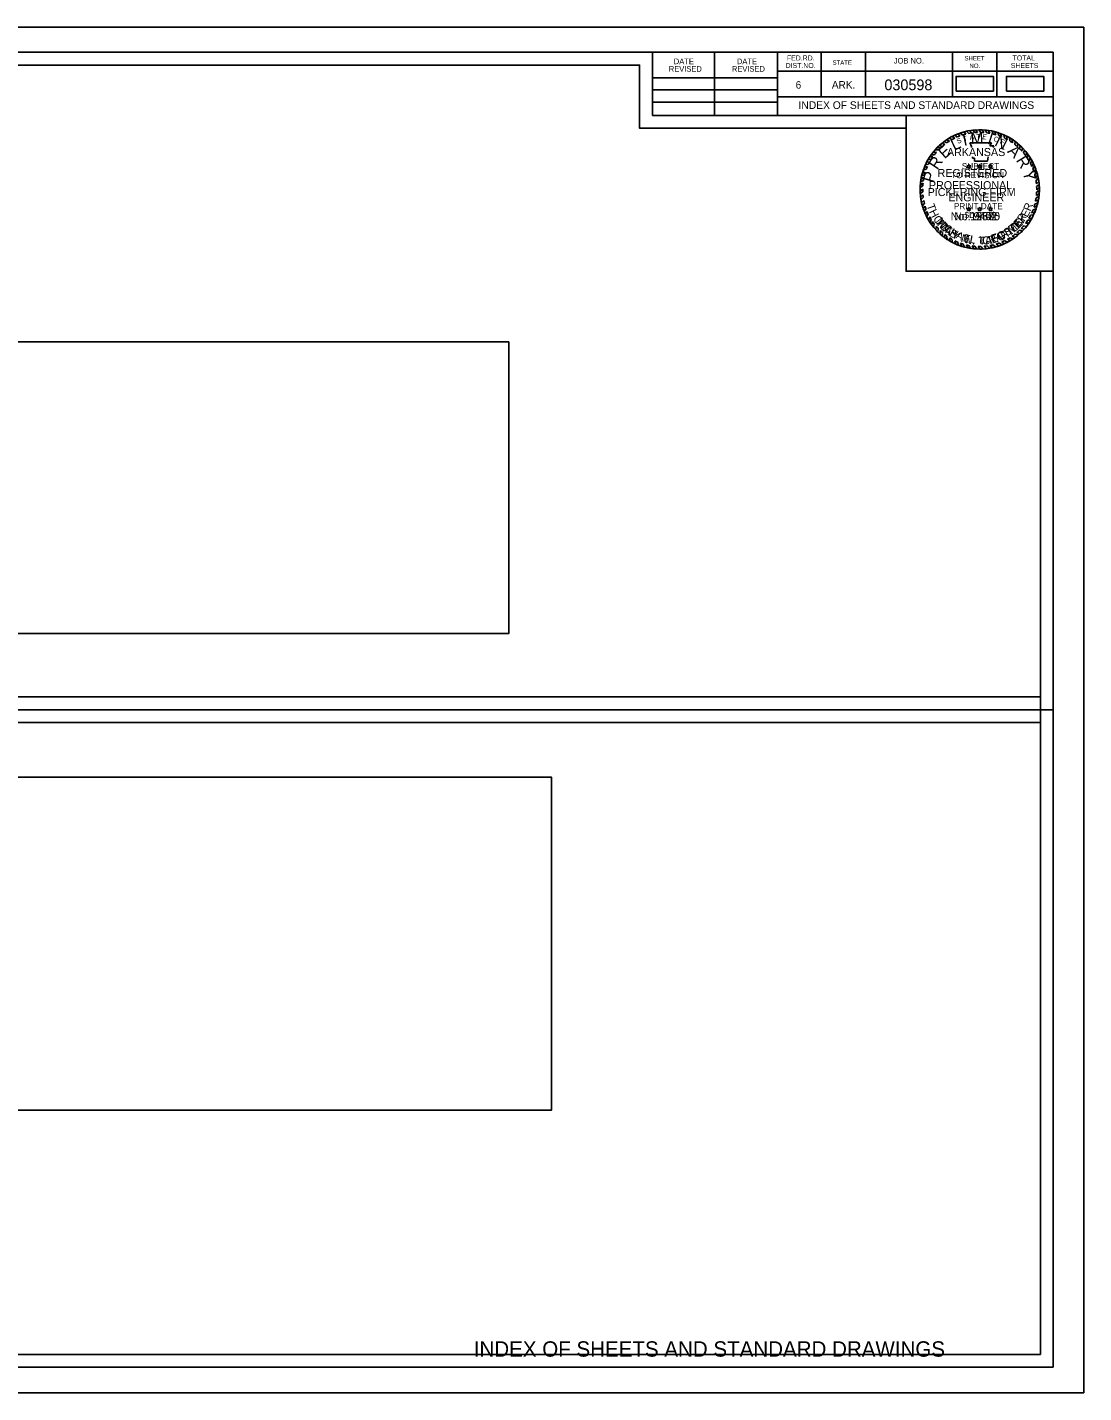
# Model space of a CAD drawing. Extents: x 1369905 to 1370238, y 380119 to 380332.
# Drawn here: x 1370072.9 to 1370238, y 380119.1 to 380332.4 of the extents above; entities that cross this region are included whole.
import ezdxf

# ---------------------------------------------------------------- set-up
doc = ezdxf.new("R2010")
doc.units = 0
for name, color, linetype in [('Default', 7, 'Continuous'), ('R_Border', 7, 'Continuous'), ('R_Border Notes', 7, 'Continuous'), ('R_Border Plan-Plan', 7, 'Continuous'), ('R_Border Title', 7, 'Continuous'), ('R_No Plot', 7, 'Continuous'), ('STAMP_PE_CRAFTON', 7, 'Continuous'), ('STAMP_PE_FOSTER', 7, 'Continuous'), ('STAMP_PE_SEAL-INFO', 7, 'Continuous'), ('STAMP_PE_TAEGTMEYER', 7, 'Continuous'), ('STAMP_PE_TXT', 7, 'Continuous'), ('STAMP_PRELIMINARY', 7, 'Continuous')]:
    doc.layers.add(name, color=color, linetype=linetype)

msp = doc.modelspace()

# ---------------------------------------------------------------- linework, layer by layer
at = {"layer": 'Default'}
for points in [[(1370218.03, 380322.43), (1370223.87, 380322.43), (1370223.87, 380324.74), (1370218.03, 380324.74)], [(1370225.9, 380322.43), (1370231.74, 380322.43), (1370231.74, 380324.74), (1370225.9, 380324.74)], [(1370003.51, 380237.69), (1370148.12, 380237.69), (1370148.12, 380283.26), (1370003.51, 380283.26)], [(1369996.82, 380163.24), (1370154.81, 380163.24), (1370154.81, 380215.25), (1369996.82, 380215.25)]]:
    msp.add_lwpolyline(points, close=True, dxfattribs=at)
at = {"layer": 'R_Border'}
for p, q in [((1369917.04, 380328.52), (1370233.22, 380328.52)), ((1370170.58, 380318.64), (1370170.58, 380328.52)), ((1370180.26, 380318.64), (1370180.26, 380328.52)), ((1370190.12, 380328.52), (1370190.12, 380318.64)), ((1370196.96, 380328.52), (1370196.96, 380321.58)), ((1370203.9, 380328.52), (1370203.9, 380321.58)), ((1370217.48, 380328.52), (1370217.48, 380321.58)), ((1370224.42, 380328.52), (1370224.42, 380321.58)), ((1370233.22, 380123.06), (1370233.22, 380328.52)), ((1370233.22, 380325.58), (1370190.12, 380325.58)), ((1370233.22, 380325.6), (1370233.22, 380325.6)), ((1370170.58, 380324.5), (1370190.12, 380324.5)), ((1370170.58, 380322.64), (1370190.12, 380322.64)), ((1370233.22, 380321.58), (1370190.12, 380321.58)), ((1370193.08, 380321.58), (1370233.22, 380321.58)), ((1370170.58, 380320.7), (1370190.12, 380320.7)), ((1370233.22, 380318.64), (1370170.58, 380318.64)), ((1370233.22, 380123.06), (1369917.04, 380123.06))]:
    msp.add_line(p, q, dxfattribs=at)
at = {"layer": 'R_Border Plan-Plan'}
msp.add_line((1369917.04, 380225.79), (1370233.22, 380225.79), dxfattribs=at)
at = {"layer": 'R_No Plot'}
for points in [[(1369904.63, 380332.42), (1370237.97, 380332.42), (1370237.97, 380119.08), (1369904.63, 380119.08)], [(1370231.22, 380227.79), (1369919.04, 380227.79), (1369919.04, 380326.52), (1370168.58, 380326.52), (1370168.58, 380316.64), (1370186.12, 380316.64), (1370210.22, 380316.64), (1370210.22, 380294.31), (1370231.22, 380294.31)], [(1369919.04, 380326.52), (1370168.58, 380326.52), (1370168.58, 380316.64), (1370186.12, 380316.64), (1370210.22, 380316.64), (1370210.22, 380294.31), (1370231.22, 380294.31), (1370231.22, 380125.06), (1369919.04, 380125.06)], [(1370210.22, 380318.64), (1370233.22, 380318.64), (1370233.22, 380294.31), (1370210.22, 380294.31)], [(1369919.04, 380223.79), (1370231.22, 380223.79), (1370231.22, 380125.06), (1369919.04, 380125.06)]]:
    msp.add_lwpolyline(points, close=True, dxfattribs=at)
at = {"layer": 'STAMP_PE_SEAL-INFO'}
for p, q in [((1370216.56, 380314.85), (1370217, 380314.65)), ((1370216.94, 380315.09), (1370217.38, 380314.87)), ((1370217.39, 380315.34), (1370217.86, 380315.12)), ((1370217.82, 380315.56), (1370218.21, 380315.28)), ((1370218.33, 380315.77), (1370218.63, 380315.45)), ((1370218.68, 380315.9), (1370219.06, 380315.59)), ((1370219.27, 380316.08), (1370219.56, 380315.73)), ((1370219.66, 380316.18), (1370220.01, 380315.84)), ((1370220.14, 380316.28), (1370220.44, 380315.91)), ((1370220.66, 380316.35), (1370220.94, 380315.97)), ((1370221.39, 380315.99), (1370221.08, 380316.39)), ((1370221.89, 380316), (1370221.61, 380316.41)), ((1370222.35, 380315.98), (1370222.09, 380316.4)), ((1370222.85, 380315.93), (1370222.56, 380316.37)), ((1370223.28, 380315.86), (1370223.02, 380316.32)), ((1370223.84, 380315.74), (1370223.67, 380316.2)), ((1370224.24, 380315.64), (1370224.08, 380316.11)), ((1370224.69, 380315.49), (1370224.55, 380315.97)), ((1370225.11, 380315.33), (1370224.97, 380315.83)), ((1370225.57, 380315.12), (1370225.47, 380315.62)), ((1370226.02, 380314.89), (1370225.93, 380315.4)), ((1370226.41, 380314.67), (1370226.37, 380315.17)), ((1370226.84, 380314.38), (1370226.81, 380314.9)), ((1370214.41, 380312.88), (1370214.96, 380312.9)), ((1370214.76, 380313.29), (1370215.28, 380313.25)), ((1370215.08, 380313.63), (1370215.62, 380313.59)), ((1370215.42, 380313.96), (1370215.88, 380313.82)), ((1370215.76, 380314.26), (1370216.29, 380314.16)), ((1370216.14, 380314.58), (1370216.59, 380314.38)), ((1370220.19, 380314.38), (1370223.54, 380314.38)), ((1370220.31, 380314.07), (1370220.19, 380314.38)), ((1370220.42, 380313.77), (1370220.31, 380314.07)), ((1370220.42, 380313.66), (1370220.42, 380313.77)), ((1370223.54, 380314.38), (1370223.31, 380313.89)), ((1370223.31, 380313.89), (1370223.94, 380313.89)), ((1370223.94, 380313.89), (1370223.8, 380313.66)), ((1370227.2, 380314.11), (1370227.24, 380314.6)), ((1370227.65, 380313.74), (1370227.67, 380314.27)), ((1370227.96, 380313.45), (1370228.03, 380313.95)), ((1370228.32, 380313.08), (1370228.39, 380313.6)), ((1370228.59, 380312.76), (1370228.73, 380313.23)), ((1370228.92, 380312.34), (1370229.05, 380312.84)), ((1370213.05, 380310.52), (1370213.55, 380310.66)), ((1370213.23, 380310.95), (1370213.74, 380311.05)), ((1370213.42, 380311.34), (1370213.92, 380311.4)), ((1370213.65, 380311.76), (1370214.14, 380311.78)), ((1370213.9, 380312.16), (1370214.42, 380312.2)), ((1370214.13, 380312.51), (1370214.64, 380312.5)), ((1370220.62, 380311.95), (1370220.59, 380312.17)), ((1370220.93, 380311.95), (1370220.62, 380311.95)), ((1370220.93, 380311.52), (1370220.93, 380311.95)), ((1370222.96, 380311.52), (1370220.93, 380311.52)), ((1370222.98, 380311.86), (1370222.96, 380311.52)), ((1370223.05, 380312.17), (1370222.98, 380311.86)), ((1370229.14, 380312.03), (1370229.32, 380312.49)), ((1370229.45, 380311.53), (1370229.63, 380312.02)), ((1370229.65, 380311.16), (1370229.87, 380311.61)), ((1370229.88, 380310.68), (1370230.1, 380311.16)), ((1370230.02, 380310.34), (1370230.28, 380310.78)), ((1370212.92, 380308.5), (1370212.47, 380308.27)), ((1370213, 380308.95), (1370212.54, 380308.71)), ((1370212.64, 380309.2), (1370213.11, 380309.39)), ((1370212.74, 380309.61), (1370213.22, 380309.78)), ((1370212.9, 380310.11), (1370213.38, 380310.25)), ((1370230.21, 380309.79), (1370230.48, 380310.27)), ((1370230.32, 380309.43), (1370230.61, 380309.88)), ((1370230.45, 380308.87), (1370230.77, 380309.32)), ((1370230.52, 380308.49), (1370230.87, 380308.84)), ((1370212.82, 380307.64), (1370212.4, 380307.38)), ((1370212.81, 380307.14), (1370212.4, 380306.81)), ((1370212.86, 380308.06), (1370212.42, 380307.78)), ((1370212.81, 380306.74), (1370212.42, 380306.41)), ((1370230.58, 380306.13), (1370231.02, 380306.39)), ((1370230.59, 380307.98), (1370230.96, 380308.32)), ((1370230.62, 380307.56), (1370231.01, 380307.86)), ((1370230.62, 380306.64), (1370231.04, 380306.92)), ((1370230.63, 380307.05), (1370231.04, 380307.37)), ((1370212.85, 380306.24), (1370212.47, 380305.88)), ((1370212.9, 380305.81), (1370212.54, 380305.44)), ((1370212.98, 380305.35), (1370212.64, 380304.98)), ((1370213.07, 380304.93), (1370212.76, 380304.52)), ((1370213.19, 380304.49), (1370212.9, 380304.07)), ((1370230.19, 380304.3), (1370230.68, 380304.5)), ((1370230.33, 380304.79), (1370230.8, 380305)), ((1370230.44, 380305.25), (1370230.9, 380305.44)), ((1370230.53, 380305.75), (1370230.97, 380305.97)), ((1370213.33, 380304.06), (1370213.05, 380303.65)), ((1370213.5, 380303.64), (1370213.24, 380303.21)), ((1370213.67, 380303.25), (1370213.44, 380302.79)), ((1370213.91, 380302.79), (1370213.72, 380302.3)), ((1370214.14, 380302.39), (1370213.96, 380301.92)), ((1370214.35, 380302.08), (1370214.24, 380301.53)), ((1370229.23, 380302.29), (1370229.71, 380302.28)), ((1370229.4, 380302.57), (1370229.9, 380302.62)), ((1370229.68, 380303.07), (1370230.16, 380303.14)), ((1370229.84, 380303.41), (1370230.32, 380303.5)), ((1370230.05, 380303.92), (1370230.53, 380304.05)), ((1370214.63, 380301.69), (1370214.52, 380301.16)), ((1370214.93, 380301.31), (1370214.84, 380300.79)), ((1370215.23, 380300.97), (1370215.17, 380300.45)), ((1370215.56, 380300.65), (1370215.53, 380300.12)), ((1370215.9, 380300.34), (1370215.9, 380299.81)), ((1370216.26, 380300.04), (1370216.28, 380299.52)), ((1370227.27, 380300.11), (1370227.74, 380299.97)), ((1370227.54, 380300.34), (1370228.01, 380300.21)), ((1370227.95, 380300.71), (1370228.39, 380300.57)), ((1370228.2, 380300.97), (1370228.68, 380300.88)), ((1370228.58, 380301.4), (1370229.05, 380301.32)), ((1370228.89, 380301.8), (1370229.4, 380301.8)), ((1370216.6, 380299.79), (1370216.63, 380299.27)), ((1370217.02, 380299.51), (1370217.09, 380299)), ((1370217.38, 380299.3), (1370217.47, 380298.79)), ((1370217.86, 380299.05), (1370218.01, 380298.53)), ((1370218.23, 380298.89), (1370218.4, 380298.37)), ((1370218.72, 380298.69), (1370218.93, 380298.19)), ((1370219.13, 380298.56), (1370219.36, 380298.07)), ((1370219.64, 380298.42), (1370219.85, 380297.95)), ((1370220.04, 380298.33), (1370220.28, 380297.88)), ((1370220.54, 380298.25), (1370220.78, 380297.81)), ((1370220.97, 380298.2), (1370221.25, 380297.78)), ((1370221.46, 380298.18), (1370221.76, 380297.76)), ((1370221.92, 380298.18), (1370222.26, 380297.78)), ((1370222.44, 380298.2), (1370222.76, 380297.82)), ((1370222.87, 380298.25), (1370223.25, 380297.89)), ((1370223.32, 380298.32), (1370223.71, 380297.98)), ((1370223.81, 380298.42), (1370224.19, 380298.1)), ((1370224.27, 380298.55), (1370224.69, 380298.25)), ((1370224.76, 380298.71), (1370225.21, 380298.44)), ((1370225.18, 380298.87), (1370225.61, 380298.61)), ((1370225.64, 380299.08), (1370226.13, 380298.87)), ((1370226.05, 380299.3), (1370226.47, 380299.06)), ((1370226.47, 380299.54), (1370226.91, 380299.35)), ((1370226.81, 380299.77), (1370227.25, 380299.58))]:
    msp.add_line(p, q, dxfattribs=at)
for radius, start, end in [(9.32, 123.6199, 126.5906), (9.32, 117.6544, 120.8099), (8.91, 115.6869, 119.1583), (9.32, 111.3124, 114.7026), (8.91, 110.3086, 113.1659), (9.32, 105.2339, 109.0352), (8.91, 104.0352, 107.3615), (9.32, 99.7525, 102.7765), (8.91, 98.258, 101.0329), (9.32, 93.9381, 96.5517), (8.91, 92.1102, 95.0367), (9.32, 87.7298, 90.6707), (8.91, 85.9628, 88.9097), (9.32, 81.9732, 84.8236), (8.91, 79.9264, 82.696), (9.32, 75.3125, 77.9426), (8.91, 73.5575, 76.2314), (9.32, 69.6061, 72.3058), (8.91, 67.6248, 70.504), (9.32, 63.1329, 66.2704), (8.91, 61.1558, 64.3784), (9.32, 56.9003, 60.0942), (9.32, 141.6056, 144.4486), (8.91, 139.301, 142.5873), (9.32, 135.4021, 138.3031), (8.91, 133.1331, 136.2562), (9.32, 129.7326, 132.5376), (8.91, 127.5297, 130.9683), (8.91, 121.9746, 125.11), (8.91, 54.9238, 58.2702), (8.91, 48.3016, 52.0395), (9.32, 50.3492, 53.7159), (8.91, 42.2212, 45.5512), (9.32, 44.3405, 47.3929), (8.91, 36.135, 39.5311), (9.32, 38.1247, 41.2316), (9.32, 152.864, 155.5189), (8.91, 156.3402, 159.2319), (9.32, 147.0072, 149.899), (8.91, 151.0315, 153.573), (8.91, 145.0197, 148.2104), (8.91, 29.9032, 33.6645), (9.32, 31.9614, 35.4294), (8.91, 23.7732, 27.2211), (9.32, 25.9391, 29.0125), (9.32, 19.9538, 23.3141), (9.32, 170.0003, 172.6878), (9.32, 164.3068, 166.894), (9.32, 158.4077, 161.0701), (8.91, 167.9048, 170.9039), (8.91, 162.4331, 165.0013), (8.91, 17.6802, 21.4251), (8.91, 11.5444, 15.2364), (8.91, 5.7599, 9.0606), (9.32, 13.8421, 17.4447), (9.32, 7.5852, 10.8621), (9.32, 175.7409, 178.2066), (9.32, 181.7251, 184.1626), (8.91, 179.6454, 182.2633), (8.91, 173.73, 176.4734), (8.91, 353.8632, 357.1274), (8.91, 359.7329, 3.0639), (9.32, 1.7215, 4.7268), (9.32, 355.7156, 358.9569), (9.32, 187.4204, 190.1927), (9.32, 193.0369, 195.9973), (8.91, 185.4539, 188.234), (8.91, 191.2274, 193.9858), (8.91, 196.9675, 199.8353), (8.91, 341.777, 345.0925), (8.91, 348.0778, 351.3435), (9.32, 343.8925, 347.035), (9.32, 349.8305, 353.0885), (9.32, 198.8967, 201.6281), (9.32, 204.5479, 207.4328), (8.91, 202.7761, 205.4791), (9.32, 210.8636, 213.6571), (8.91, 208.7883, 211.7934), (8.91, 214.1838, 217.2747), (8.91, 323.5851, 327.4407), (8.91, 329.5549, 333.2076), (9.32, 325.4405, 328.9872), (8.91, 335.6038, 339.1858), (9.32, 331.4037, 334.9332), (9.32, 337.3837, 340.9933), (9.32, 216.6115, 219.491), (9.32, 222.48, 225.3801), (8.91, 220.3909, 223.3056), (9.32, 228.3665, 231.348), (8.91, 226.2494, 229.2407), (8.91, 232.229, 234.9336), (8.91, 304.823, 308.5143), (9.32, 306.3721, 310.208), (8.91, 310.7744, 314.3161), (9.32, 312.4518, 315.6633), (8.91, 316.6531, 320.3711), (9.32, 318.2846, 321.8043), (9.32, 234.295, 236.9452), (8.91, 238.2223, 240.8353), (9.32, 240.1977, 242.8613), (8.91, 244.3204, 246.9486), (9.32, 246.576, 249.1558), (8.91, 250.3491, 253.1216), (9.32, 252.5967, 255.3252), (8.91, 256.505, 259.1192), (9.32, 258.4433, 261.1398), (8.91, 262.3783, 265.2012), (9.32, 264.1978, 267.1009), (8.91, 268.3215, 271.277), (9.32, 270.2548, 273.3361), (8.91, 274.6157, 277.4486), (9.32, 276.4239, 279.4357), (8.91, 280.3459, 283.5814), (9.32, 282.3199, 285.3702), (8.91, 286.6423, 289.9783), (9.32, 288.5709, 291.9733), (8.91, 292.8745, 296.1185), (9.32, 294.6481, 298.2166), (8.91, 299.0768, 302.1724), (9.32, 300.621, 303.8703)]:
    msp.add_arc((1370221.72, 380307.09), radius, start, end, dxfattribs=at)
at = {"layer": 'STAMP_PE_TXT'}
for p, q in [((1370219.9, 380310.66), (1370219.7, 380310.8)), ((1370219.7, 380310.8), (1370219.95, 380310.8)), ((1370219.82, 380310.43), (1370219.9, 380310.66)), ((1370220.02, 380310.57), (1370219.82, 380310.43)), ((1370219.95, 380310.8), (1370220.02, 380311.04)), ((1370220.02, 380311.04), (1370220.1, 380310.8)), ((1370220.22, 380310.43), (1370220.02, 380310.57)), ((1370220.1, 380310.8), (1370220.34, 380310.8)), ((1370220.34, 380310.8), (1370220.14, 380310.66)), ((1370220.14, 380310.66), (1370220.22, 380310.43)), ((1370221.6, 380310.66), (1370221.4, 380310.8)), ((1370221.4, 380310.8), (1370221.64, 380310.8)), ((1370221.52, 380310.43), (1370221.6, 380310.66)), ((1370221.72, 380310.57), (1370221.52, 380310.43)), ((1370221.64, 380310.8), (1370221.72, 380311.04)), ((1370221.72, 380311.04), (1370221.79, 380310.8)), ((1370221.92, 380310.43), (1370221.72, 380310.57)), ((1370221.79, 380310.8), (1370222.04, 380310.8)), ((1370222.04, 380310.8), (1370221.84, 380310.66)), ((1370221.84, 380310.66), (1370221.92, 380310.43)), ((1370223.29, 380310.66), (1370223.1, 380310.8)), ((1370223.1, 380310.8), (1370223.34, 380310.8)), ((1370223.22, 380310.43), (1370223.29, 380310.66)), ((1370223.42, 380310.57), (1370223.22, 380310.43)), ((1370223.34, 380310.8), (1370223.42, 380311.04)), ((1370223.42, 380311.04), (1370223.49, 380310.8)), ((1370223.62, 380310.43), (1370223.42, 380310.57)), ((1370223.49, 380310.8), (1370223.74, 380310.8)), ((1370223.74, 380310.8), (1370223.54, 380310.66)), ((1370223.54, 380310.66), (1370223.62, 380310.43)), ((1370219.95, 380304.1), (1370220.02, 380304.33)), ((1370220.02, 380304.33), (1370220.1, 380304.1)), ((1370221.64, 380304.1), (1370221.72, 380304.33)), ((1370221.72, 380304.33), (1370221.79, 380304.1)), ((1370223.34, 380304.1), (1370223.42, 380304.33)), ((1370223.42, 380304.33), (1370223.49, 380304.1)), ((1370219.9, 380303.95), (1370219.7, 380304.1)), ((1370219.7, 380304.1), (1370219.95, 380304.1)), ((1370219.82, 380303.72), (1370219.9, 380303.95)), ((1370220.02, 380303.86), (1370219.82, 380303.72)), ((1370220.22, 380303.72), (1370220.02, 380303.86)), ((1370220.1, 380304.1), (1370220.34, 380304.1)), ((1370220.34, 380304.1), (1370220.14, 380303.95)), ((1370220.14, 380303.95), (1370220.22, 380303.72)), ((1370221.6, 380303.95), (1370221.4, 380304.1)), ((1370221.4, 380304.1), (1370221.64, 380304.1)), ((1370221.52, 380303.72), (1370221.6, 380303.95)), ((1370221.72, 380303.86), (1370221.52, 380303.72)), ((1370221.92, 380303.72), (1370221.72, 380303.86)), ((1370221.79, 380304.1), (1370222.04, 380304.1)), ((1370222.04, 380304.1), (1370221.84, 380303.95)), ((1370221.84, 380303.95), (1370221.92, 380303.72)), ((1370223.29, 380303.95), (1370223.1, 380304.1)), ((1370223.1, 380304.1), (1370223.34, 380304.1)), ((1370223.22, 380303.72), (1370223.29, 380303.95)), ((1370223.42, 380303.86), (1370223.22, 380303.72)), ((1370223.62, 380303.72), (1370223.42, 380303.86)), ((1370223.49, 380304.1), (1370223.74, 380304.1)), ((1370223.74, 380304.1), (1370223.54, 380303.95)), ((1370223.54, 380303.95), (1370223.62, 380303.72))]:
    msp.add_line(p, q, dxfattribs=at)
at = {"layer": 'STAMP_PRELIMINARY'}
msp.add_circle((1370221.72, 380307.09), 9.32, dxfattribs=at)

# ---------------------------------------------------------------- texts
at = {"layer": 'R_Border'}
for s, height, p in [('FED.RD.', 0.782, (1370191.6, 380327.24)), ('JOB NO.', 0.879, (1370208.3, 380326.76)), ('SHEET', 0.684, (1370219.34, 380327.24)), ('TOTAL', 0.782, (1370226.86, 380327.24)), ('REVISED', 0.879, (1370173.14, 380325.48)), ('DATE', 0.879, (1370173.92, 380326.66)), ('REVISED', 0.879, (1370183, 380325.48)), ('DATE', 0.879, (1370183.78, 380326.66)), ('DIST.NO.', 0.782, (1370191.4, 380326.06)), ('STATE', 0.684, (1370198.72, 380326.56)), ('NO.', 0.684, (1370220.12, 380326.06)), ('SHEETS', 0.782, (1370226.58, 380326.06)), ('6', 1.17, (1370192.96, 380322.84)), ('ARK.', 1.172, (1370198.62, 380322.84))]:
    msp.add_text(s, height=height, dxfattribs=at).set_placement(p)
at = {"layer": 'R_Border Notes'}
for s, height, p in [('030598', 1.68, (1370206.83, 380322.59)), ('INDEX OF SHEETS AND STANDARD DRAWINGS', 1.2, (1370193.41, 380319.66))]:
    msp.add_text(s, height=height, dxfattribs=at).set_placement(p)
at = {"layer": 'R_Border Title'}
msp.add_text('INDEX OF SHEETS AND STANDARD DRAWINGS', height=2.4, dxfattribs=at).set_placement((1370142.66, 380124.71))
at = {"layer": 'STAMP_PE_CRAFTON'}
for s, rotation, p in [('T', 310.7442, (1370214.69, 380301.98)), ('N', 49.2411, (1370228, 380301.11)), ('O', 317.6422, (1370215.35, 380301.17)), ('N', 324.4537, (1370216.2, 380300.39)), ('Y', 331.1686, (1370217.23, 380299.67)), ('N', 347.4752, (1370219.29, 380298.76)), ('R', 14.8189, (1370223.29, 380298.54)), ('A', 20.5125, (1370224.4, 380298.84)), ('F', 28.7821, (1370225.38, 380299.22)), ('T', 34.1136, (1370226.3, 380299.73)), ('O', 41.8391, (1370227.15, 380300.33)), ('.', 356.8926, (1370220.52, 380298.48)), ('C', 6.0117, (1370222.19, 380298.43))]:
    msp.add_text(s, height=1.25, rotation=rotation, dxfattribs=at).set_placement(p)
msp.add_text('No. 12370', height=1.25, dxfattribs=at).set_placement((1370217.18, 380302.28))
at = {"layer": 'STAMP_PE_FOSTER'}
for s, rotation, p in [('M', 308.339, (1370214.84, 380302.11)), ('E', 46.9613, (1370227.72, 380301.08)), ('R', 54.5031, (1370228.44, 380301.9)), ('I', 314.1842, (1370215.63, 380301.17)), ('C', 319.8733, (1370215.99, 380300.82)), ('H', 327.7235, (1370216.92, 380300.08)), ('A', 335.7276, (1370217.9, 380299.5)), ('E', 343.5779, (1370219.03, 380299.03)), ('L', 350.8115, (1370220.09, 380298.75)), ('F', 15.8691, (1370223.75, 380298.84)), ('O', 23.719, (1370224.8, 380299.17)), ('S', 31.7234, (1370225.91, 380299.7)), ('T', 39.4194, (1370226.86, 380300.33)), ('L', 1.2666, (1370221.63, 380298.6)), ('.', 6.8035, (1370222.68, 380298.65))]:
    msp.add_text(s, height=1.2, rotation=rotation, dxfattribs=at).set_placement(p)
msp.add_text('No. 9402', height=1.25, dxfattribs=at).set_placement((1370217.7, 380302.28))
at = {"layer": 'STAMP_PE_TAEGTMEYER'}
for s, rotation, p in [('T', 289.646, (1370213.41, 380304.6)), ('R', 69.57, (1370229.66, 380303.6)), ('H', 296.7339, (1370213.77, 380303.61)), ('O', 303.7708, (1370214.37, 380302.5)), ('M', 314.2033, (1370215.02, 380301.55)), ('E', 46.8094, (1370227.76, 380300.86)), ('Y', 53.9986, (1370228.5, 380301.68)), ('E', 63.0984, (1370229.17, 380302.62)), ('A', 321.0594, (1370215.98, 380300.59)), ('S', 327.8239, (1370216.81, 380299.95)), ('N', 344.2727, (1370218.71, 380298.94)), ('E', 17.6836, (1370223.67, 380298.62)), ('G', 23.3052, (1370224.72, 380298.95)), ('T', 31.466, (1370225.82, 380299.44)), ('M', 39.3, (1370226.72, 380299.99)), ('.', 350.6464, (1370219.92, 380298.61)), ('T', 3.0061, (1370221.58, 380298.41)), ('A', 8.9826, (1370222.63, 380298.46))]:
    msp.add_text(s, height=1.25, rotation=rotation, dxfattribs=at).set_placement(p)
msp.add_text('No. 19605', height=1.25, dxfattribs=at).set_placement((1370217.18, 380302.28))
at = {"layer": 'STAMP_PE_TXT'}
for s, rotation, p in [('S', 23.5541, (1370218.32, 380314.19)), ('T', 16.311, (1370219.24, 380314.56)), ('A', 9.0679, (1370220.2, 380314.82)), ('T', 1.8248, (1370221.19, 380314.95)), ('E', 355.2002, (1370222.1, 380314.95)), ('O', 342.2506, (1370223.83, 380314.68)), ('F', 335.0075, (1370224.79, 380314.34))]:
    msp.add_text(s, height=0.781, rotation=rotation, dxfattribs=at).set_placement(p)
for s, p in [('ARKANSAS', (1370216.61, 380312.3)), ('REGISTERED', (1370215.14, 380309.03)), ('PROFESSIONAL', (1370213.79, 380307.13)), ('ENGINEER', (1370216.83, 380305.23))]:
    msp.add_text(s, height=1.25, dxfattribs=at).set_placement(p)
at = {"layer": 'STAMP_PRELIMINARY'}
for s, rotation, p in [('L', 25.513, (1370217.73, 380313.11)), ('I', 12.5248, (1370219.26, 380313.87)), ('M', 3.1074, (1370220.35, 380314.18)), ('I', 342.3164, (1370222.82, 380314.25)), ('N', 333.9382, (1370223.93, 380313.98)), ('E', 42.3578, (1370216.25, 380311.78)), ('A', 315.6579, (1370225.96, 380312.95)), ('R', 56.2292, (1370215.09, 380310.05)), ('R', 301.3831, (1370227.33, 380311.64)), ('P', 73.913, (1370214.54, 380308.03)), ('Y', 283.2593, (1370228.42, 380309.85))]:
    msp.add_text(s, height=1.8, rotation=rotation, dxfattribs=at).set_placement(p)
for s, height, p in [('SUBJECT', 0.96, (1370218.92, 380310.24)), ('TO REVISION', 0.96, (1370217.25, 380308.85)), ('PICKERING FIRM', 1.25, (1370213.59, 380306.05)), ('PRINT DATE', 0.96, (1370217.68, 380304)), ('$DATE$', 0.96, (1370219.35, 380302.62))]:
    msp.add_text(s, height=height, dxfattribs=at).set_placement(p)

doc.saveas('drawing.dxf')
